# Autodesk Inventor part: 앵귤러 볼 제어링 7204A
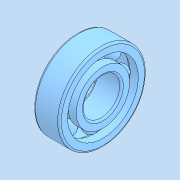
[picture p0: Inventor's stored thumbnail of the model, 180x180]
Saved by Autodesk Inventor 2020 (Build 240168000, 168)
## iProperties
Created: 2024-11
Part Number: 앵귤러 볼 제어링 7204A
Material: 강철, 연강
Description: 앵귤러 콘택트 볼 베어링
Document SubType Name: Modeling
Designer: 1강의실14
Density: 7.85 g/cm^3
Appearance: 기본값
Author: jhkim
Sending System: Autodesk Inventor 2025
Preprocessor: ST-DEVELOPER v20
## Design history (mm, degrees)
node "앵귤러 볼 제어링 7204A1"
node "솔리드1"
node "솔리드2"
node "솔리드3"
node "솔리드4"
node "솔리드5"
node "솔리드6"
node "솔리드7"
node "솔리드8"
node "솔리드9"
node "솔리드10"
body "Solid1"
node "Solid1:1"
node "Solid1:2"
node "Solid1:3"
node "Solid1:4"
node "Solid1:5"
node "Solid1:6"
node "Solid1:7"
node "Solid1:8"
node "Solid1:9"
